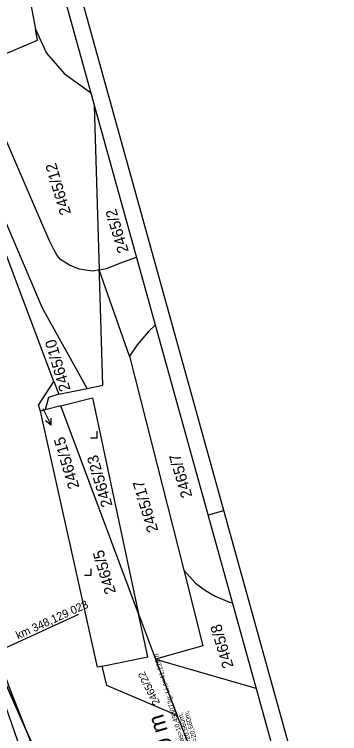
# Model space of a CAD drawing. Extents: x -821057 to -820632, y -1070881 to -1069829.
# Drawn here: x -820805.2 to -820755.2, y -1070369.4 to -1070259 of the extents above; entities that cross this region are included whole.
import ezdxf

# ---------------------------------------------------------------- set-up
doc = ezdxf.new("R2010")
doc.units = 0
for name, color, linetype in [('Hranice kat_území', 7, 'Continuous'), ('Hranice parcel', 7, 'Continuous'), ('Nabyvatel_SZ', 7, 'Continuous'), ('Parcelní čísla', 7, 'Continuous'), ('Pop  PČ popisy', 7, 'Continuous'), ('PS-11-02-31', 7, 'Continuous'), ('PS-11-02-41', 7, 'Continuous'), ('PS-11-02-92', 7, 'Continuous'), ('Rám', 7, 'Continuous'), ('SO-11-10-01', 7, 'Continuous'), ('SO-11-50-01', 7, 'Continuous'), ('SO-11-79-01', 7, 'Continuous'), ('SO-11-86-01', 7, 'Continuous'), ('UMVZST CD k SZ', 7, 'Continuous'), ('Značky kultur', 7, 'Continuous')]:
    doc.layers.add(name, color=color, linetype=linetype)

msp = doc.modelspace()

# ---------------------------------------------------------------- linework, layer by layer
at = {"layer": 'Hranice kat_území'}
for p, q in [((-820799.14, -1070315.36), (-820812.1, -1070280.9)), ((-820792.39, -1070359.23), (-820801.15, -1070319.91)), ((-820791.67, -1070359.08), (-820792.39, -1070359.23)), ((-820765.05, -1070404.29), (-820780.16, -1070366.62))]:
    msp.add_line(p, q, dxfattribs=at)
for points in [[(-820801.15, -1070319.91), (-820801.45, -1070319), (-820799.14, -1070315.36)], [(-820780.16, -1070366.62), (-820790.95, -1070362.05), (-820791.67, -1070359.08)]]:
    msp.add_lwpolyline(points, dxfattribs=at)
at = {"layer": 'Hranice parcel'}
for p, q in [((-820803, -1070255.5), (-820801.94, -1070261.25)), ((-820793.46, -1070270.97), (-820793.46, -1070270.97)), ((-820792.91, -1070272.96), (-820792.91, -1070272.96)), ((-820786.43, -1070296.28), (-820786.43, -1070296.28)), ((-820787.47, -1070311.48), (-820792.13, -1070298.22)), ((-820783.53, -1070306.73), (-820783.53, -1070306.73)), ((-820787.47, -1070311.48), (-820779.15, -1070344.32)), ((-820799.14, -1070315.36), (-820798.35, -1070317.32)), ((-820798.35, -1070317.32), (-820793.99, -1070316.42)), ((-820798.04, -1070319.1), (-820800.46, -1070319.73)), ((-820786.11, -1070351.02), (-820798.04, -1070319.1)), ((-820800.46, -1070319.73), (-820801.15, -1070319.91)), ((-820771.69, -1070349.33), (-820771.69, -1070349.33)), ((-820786.11, -1070351.02), (-820783.5, -1070358)), ((-820783.5, -1070358), (-820768.05, -1070362.44)), ((-820783.5, -1070358), (-820780.16, -1070366.62)), ((-820768.05, -1070362.44), (-820768.05, -1070362.44))]:
    msp.add_line(p, q, dxfattribs=at)
for points in [[(-820792.13, -1070298.22), (-820793, -1070298.4), (-820793.95, -1070298.3), (-820795.2, -1070298.1), (-820796.7, -1070297.5), (-820798.1, -1070296.6), (-820798.6, -1070296), (-820799.1, -1070295.1), (-820799.82, -1070293.66), (-820804.97, -1070281.8), (-820809.25, -1070271.85), (-820811.2, -1070266.98), (-820801.63, -1070262.92), (-820801.94, -1070261.25)], [(-820801.94, -1070261.25), (-820800.23, -1070264.95), (-820797.52, -1070268.04), (-820793.46, -1070270.97)], [(-820792.91, -1070272.96), (-820792.13, -1070298.22)], [(-820793.99, -1070316.42), (-820800.87, -1070304.08), (-820809.66, -1070283.54), (-820813.53, -1070273.91), (-820815.71, -1070274.99)], [(-820792.13, -1070298.22), (-820791, -1070298), (-820788.84, -1070297.13), (-820786.43, -1070296.28)], [(-820793.99, -1070316.42), (-820791.57, -1070315.92), (-820792.1, -1070299.04), (-820792.13, -1070298.22)], [(-820783.53, -1070306.73), (-820784.56, -1070307.68), (-820786.32, -1070309.72), (-820787.47, -1070311.48)], [(-820798.35, -1070317.32), (-820799.93, -1070317.83), (-820800.46, -1070319.73)], [(-820798.04, -1070319.1), (-820797.62, -1070318.99), (-820793.2, -1070317.84), (-820786.11, -1070351.02)], [(-820779.15, -1070344.32), (-820776.21, -1070355.93), (-820783.5, -1070358)], [(-820779.15, -1070344.32), (-820777.33, -1070346.31), (-820775.83, -1070347.45), (-820774.3, -1070348.31), (-820772.13, -1070349.23), (-820771.69, -1070349.33)], [(-820791.67, -1070359.08), (-820784.69, -1070357.66), (-820786.11, -1070351.02)]]:
    msp.add_lwpolyline(points, dxfattribs=at)
at = {"layer": 'Nabyvatel_SZ'}
msp.add_lwpolyline([(-820782.06, -1070569.19), (-820823.93, -1070391.03), (-820824.95, -1070387.21), (-820826.08, -1070382.39), (-820815.22, -1070377.53), (-820822.07, -1070360.7), (-820836.66, -1070328.48), (-820839.3, -1070322.5), (-820846.11, -1070309.46), (-820851.46, -1070300.37), (-820856.81, -1070291.29), (-820843.48, -1070284.13), (-820833.99, -1070279.04), (-820832.86, -1070278.44), (-820830.46, -1070283.22), (-820825.29, -1070295.05), (-820815.49, -1070325.84), (-820807.6, -1070359.39), (-820795.41, -1070386.91), (-820791.18, -1070389.77), (-820780.82, -1070405.78), (-820777.68, -1070442.4), (-820774.11, -1070459), (-820761.04, -1070511.47)], dxfattribs=at)
at = {"layer": 'Pop  PČ popisy'}
for p, q in [((-820800.8, -1070319.48), (-820799.54, -1070322.07)), ((-820799.54, -1070322.07), (-820800.39, -1070321.42)), ((-820799.54, -1070322.07), (-820799.53, -1070321))]:
    msp.add_line(p, q, dxfattribs=at)
at = {"layer": 'PS-11-02-31'}
msp.add_lwpolyline([(-820834.74, -1070280.72), (-820830.77, -1070287.4), (-820826.6, -1070295.78), (-820822.74, -1070307.42), (-820822.4, -1070310.54), (-820820.82, -1070316.36), (-820815.08, -1070335.82), (-820806.04, -1070362.21), (-820801.05, -1070374.78), (-820795.98, -1070387.28), (-820794.84, -1070388), (-820792.15, -1070393.19), (-820783.48, -1070412.23), (-820783.6, -1070416.46), (-820783.6, -1070418.02), (-820782.43, -1070424.35)], dxfattribs=at)
at = {"layer": 'PS-11-02-41'}
msp.add_lwpolyline([(-820882.99, -1070201.13), (-820875.54, -1070207.75), (-820872.79, -1070212.31), (-820866.57, -1070222.1), (-820863.69, -1070232.23), (-820854.15, -1070247.2), (-820844.78, -1070263.71), (-820834.74, -1070280.72), (-820830.77, -1070287.4), (-820826.6, -1070295.78), (-820822.74, -1070307.42), (-820822.4, -1070310.54), (-820820.82, -1070316.36), (-820815.08, -1070335.82), (-820806.04, -1070362.21), (-820801.05, -1070374.78), (-820795.98, -1070387.28), (-820794.84, -1070388), (-820792.15, -1070393.19), (-820783.48, -1070412.23), (-820783.6, -1070416.46), (-820783.6, -1070418.02), (-820782.43, -1070424.35)], dxfattribs=at)
at = {"layer": 'PS-11-02-92'}
msp.add_lwpolyline([(-820882.99, -1070201.13), (-820875.54, -1070207.75), (-820872.79, -1070212.31), (-820866.57, -1070222.1), (-820863.69, -1070232.23), (-820854.15, -1070247.2), (-820844.78, -1070263.71), (-820834.74, -1070280.72), (-820830.77, -1070287.4), (-820826.6, -1070295.78), (-820822.74, -1070307.42), (-820822.4, -1070310.54), (-820820.82, -1070316.36), (-820815.08, -1070335.82), (-820806.04, -1070362.21), (-820801.05, -1070374.78), (-820795.98, -1070387.28), (-820794.84, -1070388), (-820792.15, -1070393.19), (-820783.48, -1070412.23), (-820783.6, -1070416.46), (-820783.6, -1070418.02), (-820782.43, -1070424.35)], dxfattribs=at)
at = {"layer": 'Rám'}
msp.add_line((-820773.02, -1070335.22), (-820775.42, -1070335.89), dxfattribs=at)
for points in [[(-821000.43, -1070071.48), (-820857.35, -1070031.72), (-820632.46, -1070841.06), (-820775.54, -1070880.81)], [(-820997.35, -1070073.22), (-820859.09, -1070034.8), (-820635.54, -1070839.32), (-820773.8, -1070877.73)]]:
    msp.add_lwpolyline(points, close=True, dxfattribs=at)
at = {"layer": 'SO-11-10-01'}
msp.add_line((-820795.33, -1070351.14), (-820818.09, -1070361.48), dxfattribs=at)
msp.add_ellipse((-821045.68, -1070464.9), major_axis=(-139.53, 207.44), ratio=0.999954, start_param=4.381904, end_param=4.546806, dxfattribs=at)
at = {"layer": 'SO-11-50-01'}
msp.add_lwpolyline([(-820815.77, -1070338.8), (-820798.17, -1070389.42), (-820789.14, -1070415.39), (-820782.76, -1070425.41), (-820778.11, -1070440.81), (-820778.3, -1070451.36), (-820766.96, -1070499.85)], dxfattribs=at)
at = {"layer": 'SO-11-79-01'}
msp.add_lwpolyline([(-820761.04, -1070511.48), (-820774.11, -1070459), (-820777.68, -1070442.4), (-820780.82, -1070405.78), (-820791.18, -1070389.77), (-820795.41, -1070386.91), (-820807.6, -1070359.39), (-820815.49, -1070325.84), (-820825.29, -1070295.05), (-820830.46, -1070283.22), (-820832.86, -1070278.44)], dxfattribs=at)
at = {"layer": 'SO-11-86-01'}
msp.add_lwpolyline([(-820854.15, -1070247.2), (-820844.78, -1070263.71), (-820834.74, -1070280.72), (-820830.77, -1070287.4), (-820826.6, -1070295.78), (-820822.74, -1070307.42), (-820822.4, -1070310.54), (-820820.82, -1070316.36), (-820815.08, -1070335.82), (-820806.04, -1070362.21), (-820801.05, -1070374.78), (-820795.98, -1070387.28), (-820794.84, -1070388), (-820792.15, -1070393.19), (-820783.48, -1070412.23), (-820783.6, -1070416.46), (-820783.6, -1070418.02), (-820782.43, -1070424.35), (-820780.96, -1070434.38), (-820773.91, -1070463.73), (-820769.35, -1070482.63), (-820764.88, -1070502.04)], dxfattribs=at)
at = {"layer": 'UMVZST CD k SZ'}
msp.add_lwpolyline([(-820761.04, -1070511.47), (-820774.11, -1070459), (-820777.68, -1070442.4), (-820780.82, -1070405.78), (-820791.18, -1070389.77), (-820795.41, -1070386.91), (-820807.6, -1070359.39), (-820815.49, -1070325.84), (-820825.29, -1070295.05), (-820830.46, -1070283.22), (-820832.86, -1070278.44), (-820833.99, -1070279.04), (-820843.48, -1070284.13), (-820856.81, -1070291.29), (-820851.46, -1070300.37), (-820846.11, -1070309.46), (-820839.3, -1070322.5), (-820836.66, -1070328.48), (-820822.07, -1070360.7), (-820815.22, -1070377.53), (-820826.08, -1070382.39), (-820824.95, -1070387.21), (-820823.93, -1070391.03), (-820782.06, -1070569.19)], dxfattribs=at)
at = {"layer": 'Značky kultur'}
for p, q in [((-820792.46, -1070324), (-820792.46, -1070323)), ((-820793.46, -1070324), (-820792.46, -1070324)), ((-820793.37, -1070345.12), (-820793.37, -1070344.12)), ((-820794.38, -1070345.12), (-820793.37, -1070345.12))]:
    msp.add_line(p, q, dxfattribs=at)

# ---------------------------------------------------------------- texts
at = {"layer": 'Parcelní čísla'}
for s, height, rotation, p in [('2465/12', 1.7, 106.7086, (-820796.46, -1070289.52)), ('2465/2', 1.7, 106.7086, (-820787.59, -1070295.36)), ('2465/10', 1.7, 106.7086, (-820796.53, -1070316.6)), ('2465/15', 1.7, 106.7086, (-820795.17, -1070331.58)), ('2465/23', 1.7, 106.7086, (-820790.08, -1070334.37)), ('2465/7', 1.7, 106.7086, (-820777.81, -1070332.96)), ('2465/17', 1.7, 106.7086, (-820783.04, -1070338.25)), ('2465/5', 1.7, 106.7086, (-820789.55, -1070347.74)), ('2465/8', 1.7, 106.7086, (-820771.47, -1070359.12)), ('2465/22', 1.139, 116.5393, (-820782.76, -1070364.69))]:
    msp.add_text(s, height=height, rotation=rotation, dxfattribs=at).set_placement(p)
at = {"layer": 'SO-11-10-01'}
for s, height, rotation, p in [('km 348,129 023', 1.25, 24.4385, (-820804.61, -1070354.98)), ('V=40km/h; D=0mm; l=76mm; alfas=10,498073g; Li,o=41,226m', 0.75, 106.528, (-820774.87, -1070384.81)), ('R=250 m', 2.5, 106.528, (-820778.49, -1070379.36)), ('n=0V; Lk=0m; T=20,660m;', 0.75, 106.528, (-820775.9, -1070377.91)), ('n=0V; Lk=0m; T=20,660m;', 0.75, 106.528, (-820774.97, -1070377.63))]:
    msp.add_text(s, height=height, rotation=rotation, dxfattribs=at).set_placement(p)

doc.saveas('drawing.dxf')
